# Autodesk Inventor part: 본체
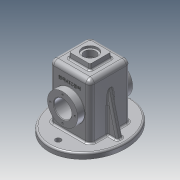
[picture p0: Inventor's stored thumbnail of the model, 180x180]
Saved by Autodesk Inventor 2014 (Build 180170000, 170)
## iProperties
Created: 2017-07
Part Number: 본체
Material: 알루미늄 6061
Document SubType Name: Modeling
Designer: user
Density: 2.71 g/cm^3
Appearance: 알루미늄 - 평지
Mass: 892.711 g
Surface Area: 987.484 cm^2
Volume: 329.414 cm^3
Author: user
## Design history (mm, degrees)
sketch "스케치1"
  geometry: C1 r 27.5 at (0, 0); 1 further point
  constraints: 1 centre point, 1 coincident
  dimensions: "d0" = 55 diameter of C1
extrude "돌출1" new body sketch "스케치1" stored distance "d1" = 100; taper "d2" = 0 deg
node "작업 평면1"
sketch "스케치2" dims "d4" = 65, "d5" = 75
  geometry: 2 further points; 1 other entity
  constraints: 1 coincident, 2 other
extrude "돌출2" join sketch "스케치2" distance "d6" = 10; taper "d7" = 0 deg
sketch "스케치3"
  geometry: L1 (-37, 37)-(37, 37); L2 (37, 37)-(37, -37); L3 (37, -37)-(-37, -37); L4 (-37, -37)-(-37, 37); L5 (-37, 37)-(37, -37); L6 (37, 37)-(-37, -37); 1 further point; 1 other entity
  constraints: 12 end point, 2 midpoint, 2 parallel, 1 horizontal, 1 perpendicular, 1 other
  dimensions: "d8" = 74 distance of L2.end L3.end; "d9" = 74 distance of L1.end L2.end
extrude "돌출3" join sketch "스케치3" distance "d10" = 100; taper "d11" = 0 deg
sketch "스케치4"
  geometry: L1 (-20, -20)-(20, -20); L2 (20, -20)-(20, 20); L3 (20, 20)-(-20, 20); L4 (-20, 20)-(-20, -20); L5 (-20, -20)-(20, 20); L6 (20, -20)-(-20, 20); 1 further point
  constraints: 12 end point, 2 midpoint, 2 parallel, 1 horizontal, 1 perpendicular
  dimensions: "d12" = 40 distance of L3.end L2.end; "d13" = 40 distance of L2.end L1.end
extrude "돌출4" join sketch "스케치4" distance "d14" = 10; taper "d15" = 0 deg
fillet "모깎기1" dims "d16" = 8
sketch "스케치5"
  geometry: L1 (-45, -75)-(-55, -75) reference; L2 (-55, -75)-(-55, 75) reference; L3 (-55, 75)-(-45, 75) reference; L4 (-45, 75)-(-45, 37) reference; L5 (-45, 37)-(-27.5, 37) reference; L6 (-27.5, 37)-(-27.5, 50) reference; L7 (-27.5, 50)-(27.5, 50) reference; L8 (27.5, 50)-(27.5, 37) reference; L9 (27.5, 37)-(55, 37) reference; L10 (55, 37)-(55, 20) reference; L11 (55, 20)-(65, 20) reference; L12 (65, 20)-(65, -20) reference; L13 (65, -20)-(55, -20) reference; L14 (55, -20)-(55, -37) reference; L15 (55, -37)-(27.5, -37) reference; L16 (27.5, -37)-(27.5, -50) reference; L17 (27.5, -50)-(-27.5, -50) reference; L18 (-27.5, -50)-(-27.5, -37) reference; L19 (-27.5, -37)-(-45, -37) reference; L20 (-45, -37)-(-45, -75) reference; L21 (-55, 32)-(50, 32); L22 (50, 32)-(50, -32); L23 (50, -32)-(-55, -32); L24 (-55, -32)-(-55, 32); 2 further points
  constraints: 8 end point, 2 parallel, 1 horizontal, 1 midpoint, 1 perpendicular, 1 point on line
  dimensions: "d17" = 5 distance between parallel lines of L10 L22; "d18" = 5 distance between parallel lines of L9 L21; "d19" = 5 distance between parallel lines of L15 L23
extrude "돌출5" cut sketch "스케치5" stored distance "d20" = 64; taper "d21" = 0 deg
node "작업 평면2"
sketch "스케치6"
  geometry: 1 further point
sketch "스케치7"
  geometry: C1 r 27.5 at (32, 55); 1 further point
  constraints: 1 centre point, 1 coincident
  dimensions: "d23" = 55 diameter of C1
extrude "돌출6" join sketch "스케치7" distance "d24" = 7; taper "d25" = -45 deg
hole "구멍1" diameter "d28" = 32; stored, may be unused: countersink angle "d32" = 90 deg, drill point angle "d34" = 118 deg; dims "d26" = 10, "d27" = 10, "d29" = 6, "d30" = 4, "d31" = 2, "d33" = 8
sketch "스케치8" dims "d35" = 45
  geometry: C1 r 27.5 at (0, 0) reference; 2 further points
  constraints: 2 vertical alignment, 1 coincident, 2 other
hole "구멍2" sketch "스케치8" at (0, 22.5) diameter "d36" = 3.242; stored, may be unused: countersink angle "d40" = 90 deg, drill point angle "d42" = 118 deg; dims "d37" = 8, "d38" = 4, "d39" = 2, "d41" = 10
sketch "스케치9"
  geometry: 2 further points
  constraints: 1 coincident
hole "구멍3" sketch "스케치9" at (0, 0) diameter "d46" = 21; stored, may be unused: countersink angle "d50" = 90 deg, drill point angle "d52" = 118 deg; dims "d47" = 8, "d48" = 28, "d49" = 4, "d51" = 10
feature "면 기울기1" dims angle "d53" = 5 deg
sketch "스케치11"
  geometry: L1 (65, -45)-(65, -55) reference; L2 (65, -55)-(32, -55) reference; L3 (32, -55)-(32, 50) reference; L4 (32, 50)-(10.5, 50) reference; L5 (10.5, 50)-(10.5, 61) reference; L6 (10.5, 61)-(14, 61) reference; L7 (14, 61)-(14, 65) reference; L8 (14, 65)-(19.125, 65) reference; L9 (19.125, 65)-(20, 55) reference; L10 (20, 55)-(37, 55) reference; L11 (37, 55)-(37, -45) reference; L12 (37, -45)-(65, -45) reference; L13 (-65, -55)-(-65, -45) reference; L14 (-65, -45)-(-37, -45) reference; L15 (-37, -45)-(-37, 55) reference; L16 (-37, 55)-(-20, 55) reference; L17 (-20, 55)-(-19.125, 65) reference; L18 (-19.125, 65)-(-14, 65) reference; L19 (-14, 65)-(-14, 61) reference; L20 (-14, 61)-(-10.5, 61) reference; L21 (-10.5, 61)-(-10.5, 50) reference; L22 (-10.5, 50)-(-32, 50) reference; L23 (-32, 50)-(-32, -55) reference; L24 (-32, -55)-(-65, -55) reference; L25 (-55, -45)-(-45.492, -6.867); 1 further point
  constraints: 2 end point, 1 point on line
  dimensions: "d54" = 10 distance from line of L25.start L13; "d55" = 14 deg angle of L13 L25
feature "리브1" sketch "스케치11" dims "d56" = 1, "d57" = 10, "d58" = 0, "d59" = 0, "d60" = 1, "d61" = 1
sketch "스케치12"
  geometry: L1 (0, 58)-(0, -58); 2 further points; 1 other entity
  constraints: 2 end point, 1 coincident, 1 midpoint, 1 vertical, 1 other
  dimensions: "d62" = 116 distance of L1.start L1.end
hole "구멍4" sketch "스케치12" at (0, -58), (0, 58) diameter "d63" = 10; stored, may be unused: countersink angle "d67" = 90 deg, drill point angle "d69" = 118 deg; dims "d64" = 8, "d65" = 28, "d66" = 4, "d68" = 10
fillet "모깎기2" dims "d70" = 3
fillet "모깎기3" dims "d71" = 3
fillet "모깎기4" dims "d72" = 3
fillet "모깎기5" dims "d73" = 3
fillet "모깎기6" dims "d74" = 8
chamfer "모따기1" distance "d77" = 1; stored, may be unused: second distance "d78" = 2, angle "d79" = 45 deg
fillet "모깎기9" dims "d80" = 3
fillet "모깎기10" dims "d81" = 3
fillet "모깎기11" dims "d82" = 3
sketch "스케치13"
  geometry: L1 (66, -89)-(66, 0) reference; L2 (45.137, 18)-(48.125, 18) reference; 1 further point
  constraints: 1 other
  dimensions: "d84" = 37 distance from line of L1 point (29, -12); "d85" = 30 distance from line of L2 point (29, -12)
feature "엠보싱1" sketch "스케치13" dims "d0" = 55, "d86" = 0.5, "d87" = 0
fillet "모깎기13" dims "d88" = 0.5
node "솔리드1"
mirror "대칭1"
pattern_circular "원형 패턴1" dims angle "d44" = 360 deg
mirror "대칭2"
mirror "대칭3"
node "절단 모서리 투영1"
node "절단 모서리 투영2"
other parameters: "d3" = -55, "d22" = 7
